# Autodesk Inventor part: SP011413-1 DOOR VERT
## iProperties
Company: MiniTec Framing Systems, LLC
Created: 2013-01
Part Number: SP011413-1 DOOR VERT
Material: Aluminum-6061
Description: PROFILE 19X45
Document SubType Name: Modeling
Designer: Administrator
Stock Number: 20.1001 PROFILE 19X45
Density: 2.71 g/cm^3
Mass: 1296.53 g
Surface Area: 2590.24 cm^2
Volume: 478.423 cm^3
FINISH: CLEAR ANODIZED
Author: Administrator
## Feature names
1. Extrusion1
